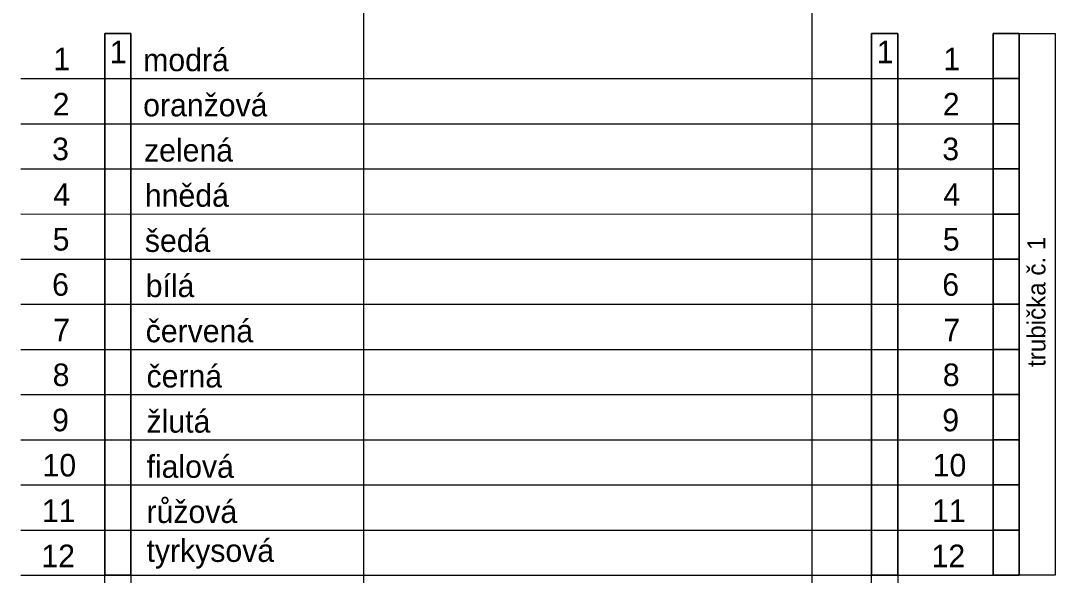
# Model space of a CAD drawing. Extents: x 1901 to 2519, y -3585 to -3154.
# Drawn here: x 2032.8 to 2113, y -3245.2 to -3202 of the extents above; entities that cross this region are included whole.
import ezdxf

# ---------------------------------------------------------------- set-up
doc = ezdxf.new("R2010")
doc.units = 0
doc.layers.add('rozvláknění', color=7, linetype='Continuous')

msp = doc.modelspace()

# ---------------------------------------------------------------- linework, layer by layer
at = {"layer": 'rozvláknění'}
for p, q in [((2032.823, -3206.524), (2108.565, -3206.527)), ((2032.823, -3210.043), (2108.565, -3210.045)), ((2032.823, -3213.561), (2108.565, -3213.563)), ((2032.823, -3217.079), (2108.565, -3217.081)), ((2032.823, -3220.597), (2108.565, -3220.599)), ((2032.823, -3224.115), (2108.565, -3224.117)), ((2032.823, -3227.634), (2108.565, -3227.636)), ((2032.823, -3231.152), (2108.565, -3231.154)), ((2032.823, -3234.67), (2108.565, -3234.672)), ((2032.823, -3238.188), (2108.565, -3238.19)), ((2032.823, -3241.706), (2108.565, -3241.708)), ((2032.823, -3245.225), (2108.565, -3245.227))]:
    msp.add_line(p, q, dxfattribs=at)
for points in [[(2014.869, -3178.545), (2059.522, -3178.544), (2059.522, -3570.656), (2014.869, -3570.656)], [(2094.462, -3178.545), (2128.46, -3178.544), (2128.46, -3571.465), (2094.462, -3571.465)], [(2041.391, -3287.481), (2039.35, -3287.481), (2039.35, -3203.008), (2041.391, -3203.008)], [(2041.391, -3245.227), (2039.35, -3245.227), (2039.35, -3203.008), (2041.391, -3203.008)], [(2101.143, -3287.481), (2099.102, -3287.481), (2099.102, -3203.008), (2101.143, -3203.008)], [(2101.143, -3245.227), (2099.102, -3245.227), (2099.102, -3203.008), (2101.143, -3203.008)], [(2108.565, -3203.008), (2110.606, -3203.008), (2110.606, -3206.527), (2108.565, -3206.527)], [(2108.565, -3203.008), (2110.606, -3203.008), (2110.606, -3206.527), (2108.565, -3206.527)], [(2110.606, -3203.008), (2113.393, -3203.008), (2113.393, -3245.223), (2110.606, -3245.223)], [(2108.565, -3206.527), (2110.606, -3206.527), (2110.606, -3210.045), (2108.565, -3210.045)], [(2108.565, -3206.527), (2110.606, -3206.527), (2110.606, -3210.045), (2108.565, -3210.045)], [(2108.565, -3210.045), (2110.606, -3210.045), (2110.606, -3213.563), (2108.565, -3213.563)], [(2108.565, -3210.045), (2110.606, -3210.045), (2110.606, -3213.563), (2108.565, -3213.563)], [(2108.565, -3213.563), (2110.606, -3213.563), (2110.606, -3217.081), (2108.565, -3217.081)], [(2108.565, -3213.563), (2110.606, -3213.563), (2110.606, -3217.081), (2108.565, -3217.081)], [(2108.565, -3217.081), (2110.606, -3217.081), (2110.606, -3220.599), (2108.565, -3220.599)], [(2108.565, -3217.081), (2110.606, -3217.081), (2110.606, -3220.599), (2108.565, -3220.599)], [(2108.565, -3220.599), (2110.606, -3220.599), (2110.606, -3224.117), (2108.565, -3224.117)], [(2108.565, -3220.599), (2110.606, -3220.599), (2110.606, -3224.117), (2108.565, -3224.117)], [(2108.565, -3224.117), (2110.606, -3224.117), (2110.606, -3227.636), (2108.565, -3227.636)], [(2108.565, -3224.117), (2110.606, -3224.117), (2110.606, -3227.636), (2108.565, -3227.636)], [(2108.565, -3227.636), (2110.606, -3227.636), (2110.606, -3231.154), (2108.565, -3231.154)], [(2108.565, -3227.636), (2110.606, -3227.636), (2110.606, -3231.154), (2108.565, -3231.154)], [(2108.565, -3231.154), (2110.606, -3231.154), (2110.606, -3234.672), (2108.565, -3234.672)], [(2108.565, -3231.154), (2110.606, -3231.154), (2110.606, -3234.672), (2108.565, -3234.672)], [(2108.565, -3234.672), (2110.606, -3234.672), (2110.606, -3238.19), (2108.565, -3238.19)], [(2108.565, -3234.672), (2110.606, -3234.672), (2110.606, -3238.19), (2108.565, -3238.19)], [(2108.565, -3238.19), (2110.606, -3238.19), (2110.606, -3241.708), (2108.565, -3241.708)], [(2108.565, -3238.19), (2110.606, -3238.19), (2110.606, -3241.708), (2108.565, -3241.708)], [(2108.565, -3241.708), (2110.606, -3241.708), (2110.606, -3245.227), (2108.565, -3245.227)], [(2108.565, -3241.708), (2110.606, -3241.708), (2110.606, -3245.227), (2108.565, -3245.227)]]:
    msp.add_lwpolyline(points, close=True, dxfattribs=at)
for points in [[(2041.391, -3203.008), (2039.35, -3203.008), (2039.35, -3245.227), (2041.391, -3245.227), (2041.391, -3203.008)], [(2041.391, -3203.008), (2039.35, -3203.008), (2039.35, -3245.227), (2041.391, -3245.227), (2041.391, -3203.008)], [(2041.391, -3203.008), (2039.35, -3203.008), (2039.35, -3245.227), (2041.391, -3245.227), (2041.391, -3203.008)], [(2041.391, -3203.008), (2039.35, -3203.008), (2039.35, -3245.227), (2041.391, -3245.227), (2041.391, -3203.008)], [(2041.391, -3203.008), (2039.35, -3203.008), (2039.35, -3245.227), (2041.391, -3245.227), (2041.391, -3203.008)], [(2041.391, -3203.008), (2039.35, -3203.008), (2039.35, -3245.227), (2041.391, -3245.227), (2041.391, -3203.008)], [(2101.143, -3203.008), (2099.102, -3203.008), (2099.102, -3245.227), (2101.143, -3245.227), (2101.143, -3203.008)], [(2101.143, -3203.008), (2099.102, -3203.008), (2099.102, -3245.227), (2101.143, -3245.227), (2101.143, -3203.008)], [(2101.143, -3203.008), (2099.102, -3203.008), (2099.102, -3245.227), (2101.143, -3245.227), (2101.143, -3203.008)], [(2101.143, -3203.008), (2099.102, -3203.008), (2099.102, -3245.227), (2101.143, -3245.227), (2101.143, -3203.008)], [(2101.143, -3203.008), (2099.102, -3203.008), (2099.102, -3245.227), (2101.143, -3245.227), (2101.143, -3203.008)], [(2101.143, -3203.008), (2099.102, -3203.008), (2099.102, -3245.227), (2101.143, -3245.227), (2101.143, -3203.008)], [(2108.565, -3206.527), (2110.606, -3206.527), (2110.606, -3203.008), (2108.565, -3203.008), (2108.565, -3206.527)], [(2108.565, -3206.527), (2110.606, -3206.527), (2110.606, -3203.008), (2108.565, -3203.008), (2108.565, -3206.527)], [(2108.565, -3206.527), (2110.606, -3206.527), (2110.606, -3203.008), (2108.565, -3203.008), (2108.565, -3206.527)], [(2108.565, -3206.527), (2110.606, -3206.527), (2110.606, -3203.008), (2108.565, -3203.008), (2108.565, -3206.527)], [(2108.565, -3206.527), (2110.606, -3206.527), (2110.606, -3203.008), (2108.565, -3203.008), (2108.565, -3206.527)], [(2108.565, -3206.527), (2110.606, -3206.527), (2110.606, -3203.008), (2108.565, -3203.008), (2108.565, -3206.527)], [(2108.565, -3206.527), (2110.606, -3206.527), (2110.606, -3203.008), (2108.565, -3203.008), (2108.565, -3206.527)], [(2108.565, -3206.527), (2110.606, -3206.527), (2110.606, -3203.008), (2108.565, -3203.008), (2108.565, -3206.527)], [(2108.565, -3206.527), (2110.606, -3206.527), (2110.606, -3203.008), (2108.565, -3203.008), (2108.565, -3206.527)], [(2108.565, -3206.527), (2110.606, -3206.527), (2110.606, -3203.008), (2108.565, -3203.008), (2108.565, -3206.527)], [(2108.565, -3210.045), (2110.606, -3210.045), (2110.606, -3206.527), (2108.565, -3206.527), (2108.565, -3210.045)], [(2108.565, -3210.045), (2110.606, -3210.045), (2110.606, -3206.527), (2108.565, -3206.527), (2108.565, -3210.045)], [(2108.565, -3210.045), (2110.606, -3210.045), (2110.606, -3206.527), (2108.565, -3206.527), (2108.565, -3210.045)], [(2108.565, -3210.045), (2110.606, -3210.045), (2110.606, -3206.527), (2108.565, -3206.527), (2108.565, -3210.045)], [(2108.565, -3210.045), (2110.606, -3210.045), (2110.606, -3206.527), (2108.565, -3206.527), (2108.565, -3210.045)], [(2108.565, -3210.045), (2110.606, -3210.045), (2110.606, -3206.527), (2108.565, -3206.527), (2108.565, -3210.045)], [(2108.565, -3210.045), (2110.606, -3210.045), (2110.606, -3206.527), (2108.565, -3206.527), (2108.565, -3210.045)], [(2108.565, -3210.045), (2110.606, -3210.045), (2110.606, -3206.527), (2108.565, -3206.527), (2108.565, -3210.045)], [(2108.565, -3210.045), (2110.606, -3210.045), (2110.606, -3206.527), (2108.565, -3206.527), (2108.565, -3210.045)], [(2108.565, -3210.045), (2110.606, -3210.045), (2110.606, -3206.527), (2108.565, -3206.527), (2108.565, -3210.045)], [(2108.565, -3213.563), (2110.606, -3213.563), (2110.606, -3210.045), (2108.565, -3210.045), (2108.565, -3213.563)], [(2108.565, -3213.563), (2110.606, -3213.563), (2110.606, -3210.045), (2108.565, -3210.045), (2108.565, -3213.563)], [(2108.565, -3213.563), (2110.606, -3213.563), (2110.606, -3210.045), (2108.565, -3210.045), (2108.565, -3213.563)], [(2108.565, -3213.563), (2110.606, -3213.563), (2110.606, -3210.045), (2108.565, -3210.045), (2108.565, -3213.563)], [(2108.565, -3213.563), (2110.606, -3213.563), (2110.606, -3210.045), (2108.565, -3210.045), (2108.565, -3213.563)], [(2108.565, -3213.563), (2110.606, -3213.563), (2110.606, -3210.045), (2108.565, -3210.045), (2108.565, -3213.563)], [(2108.565, -3213.563), (2110.606, -3213.563), (2110.606, -3210.045), (2108.565, -3210.045), (2108.565, -3213.563)], [(2108.565, -3213.563), (2110.606, -3213.563), (2110.606, -3210.045), (2108.565, -3210.045), (2108.565, -3213.563)], [(2108.565, -3213.563), (2110.606, -3213.563), (2110.606, -3210.045), (2108.565, -3210.045), (2108.565, -3213.563)], [(2108.565, -3213.563), (2110.606, -3213.563), (2110.606, -3210.045), (2108.565, -3210.045), (2108.565, -3213.563)], [(2108.565, -3217.081), (2110.606, -3217.081), (2110.606, -3213.563), (2108.565, -3213.563), (2108.565, -3217.081)], [(2108.565, -3217.081), (2110.606, -3217.081), (2110.606, -3213.563), (2108.565, -3213.563), (2108.565, -3217.081)], [(2108.565, -3217.081), (2110.606, -3217.081), (2110.606, -3213.563), (2108.565, -3213.563), (2108.565, -3217.081)], [(2108.565, -3217.081), (2110.606, -3217.081), (2110.606, -3213.563), (2108.565, -3213.563), (2108.565, -3217.081)], [(2108.565, -3217.081), (2110.606, -3217.081), (2110.606, -3213.563), (2108.565, -3213.563), (2108.565, -3217.081)], [(2108.565, -3217.081), (2110.606, -3217.081), (2110.606, -3213.563), (2108.565, -3213.563), (2108.565, -3217.081)], [(2108.565, -3217.081), (2110.606, -3217.081), (2110.606, -3213.563), (2108.565, -3213.563), (2108.565, -3217.081)], [(2108.565, -3217.081), (2110.606, -3217.081), (2110.606, -3213.563), (2108.565, -3213.563), (2108.565, -3217.081)], [(2108.565, -3217.081), (2110.606, -3217.081), (2110.606, -3213.563), (2108.565, -3213.563), (2108.565, -3217.081)], [(2108.565, -3217.081), (2110.606, -3217.081), (2110.606, -3213.563), (2108.565, -3213.563), (2108.565, -3217.081)], [(2108.565, -3220.599), (2110.606, -3220.599), (2110.606, -3217.081), (2108.565, -3217.081), (2108.565, -3220.599)], [(2108.565, -3220.599), (2110.606, -3220.599), (2110.606, -3217.081), (2108.565, -3217.081), (2108.565, -3220.599)], [(2108.565, -3220.599), (2110.606, -3220.599), (2110.606, -3217.081), (2108.565, -3217.081), (2108.565, -3220.599)], [(2108.565, -3220.599), (2110.606, -3220.599), (2110.606, -3217.081), (2108.565, -3217.081), (2108.565, -3220.599)], [(2108.565, -3220.599), (2110.606, -3220.599), (2110.606, -3217.081), (2108.565, -3217.081), (2108.565, -3220.599)], [(2108.565, -3220.599), (2110.606, -3220.599), (2110.606, -3217.081), (2108.565, -3217.081), (2108.565, -3220.599)], [(2108.565, -3220.599), (2110.606, -3220.599), (2110.606, -3217.081), (2108.565, -3217.081), (2108.565, -3220.599)], [(2108.565, -3220.599), (2110.606, -3220.599), (2110.606, -3217.081), (2108.565, -3217.081), (2108.565, -3220.599)], [(2108.565, -3220.599), (2110.606, -3220.599), (2110.606, -3217.081), (2108.565, -3217.081), (2108.565, -3220.599)], [(2108.565, -3220.599), (2110.606, -3220.599), (2110.606, -3217.081), (2108.565, -3217.081), (2108.565, -3220.599)], [(2108.565, -3224.117), (2110.606, -3224.117), (2110.606, -3220.599), (2108.565, -3220.599), (2108.565, -3224.117)], [(2108.565, -3224.117), (2110.606, -3224.117), (2110.606, -3220.599), (2108.565, -3220.599), (2108.565, -3224.117)], [(2108.565, -3224.117), (2110.606, -3224.117), (2110.606, -3220.599), (2108.565, -3220.599), (2108.565, -3224.117)], [(2108.565, -3224.117), (2110.606, -3224.117), (2110.606, -3220.599), (2108.565, -3220.599), (2108.565, -3224.117)], [(2108.565, -3224.117), (2110.606, -3224.117), (2110.606, -3220.599), (2108.565, -3220.599), (2108.565, -3224.117)], [(2108.565, -3224.117), (2110.606, -3224.117), (2110.606, -3220.599), (2108.565, -3220.599), (2108.565, -3224.117)], [(2108.565, -3224.117), (2110.606, -3224.117), (2110.606, -3220.599), (2108.565, -3220.599), (2108.565, -3224.117)], [(2108.565, -3224.117), (2110.606, -3224.117), (2110.606, -3220.599), (2108.565, -3220.599), (2108.565, -3224.117)], [(2108.565, -3224.117), (2110.606, -3224.117), (2110.606, -3220.599), (2108.565, -3220.599), (2108.565, -3224.117)], [(2108.565, -3224.117), (2110.606, -3224.117), (2110.606, -3220.599), (2108.565, -3220.599), (2108.565, -3224.117)], [(2108.565, -3227.636), (2110.606, -3227.636), (2110.606, -3224.117), (2108.565, -3224.117), (2108.565, -3227.636)], [(2108.565, -3227.636), (2110.606, -3227.636), (2110.606, -3224.117), (2108.565, -3224.117), (2108.565, -3227.636)], [(2108.565, -3227.636), (2110.606, -3227.636), (2110.606, -3224.117), (2108.565, -3224.117), (2108.565, -3227.636)], [(2108.565, -3227.636), (2110.606, -3227.636), (2110.606, -3224.117), (2108.565, -3224.117), (2108.565, -3227.636)], [(2108.565, -3227.636), (2110.606, -3227.636), (2110.606, -3224.117), (2108.565, -3224.117), (2108.565, -3227.636)], [(2108.565, -3227.636), (2110.606, -3227.636), (2110.606, -3224.117), (2108.565, -3224.117), (2108.565, -3227.636)], [(2108.565, -3227.636), (2110.606, -3227.636), (2110.606, -3224.117), (2108.565, -3224.117), (2108.565, -3227.636)], [(2108.565, -3227.636), (2110.606, -3227.636), (2110.606, -3224.117), (2108.565, -3224.117), (2108.565, -3227.636)], [(2108.565, -3227.636), (2110.606, -3227.636), (2110.606, -3224.117), (2108.565, -3224.117), (2108.565, -3227.636)], [(2108.565, -3227.636), (2110.606, -3227.636), (2110.606, -3224.117), (2108.565, -3224.117), (2108.565, -3227.636)], [(2108.565, -3231.154), (2110.606, -3231.154), (2110.606, -3227.636), (2108.565, -3227.636), (2108.565, -3231.154)], [(2108.565, -3231.154), (2110.606, -3231.154), (2110.606, -3227.636), (2108.565, -3227.636), (2108.565, -3231.154)], [(2108.565, -3231.154), (2110.606, -3231.154), (2110.606, -3227.636), (2108.565, -3227.636), (2108.565, -3231.154)], [(2108.565, -3231.154), (2110.606, -3231.154), (2110.606, -3227.636), (2108.565, -3227.636), (2108.565, -3231.154)], [(2108.565, -3231.154), (2110.606, -3231.154), (2110.606, -3227.636), (2108.565, -3227.636), (2108.565, -3231.154)], [(2108.565, -3231.154), (2110.606, -3231.154), (2110.606, -3227.636), (2108.565, -3227.636), (2108.565, -3231.154)], [(2108.565, -3231.154), (2110.606, -3231.154), (2110.606, -3227.636), (2108.565, -3227.636), (2108.565, -3231.154)], [(2108.565, -3231.154), (2110.606, -3231.154), (2110.606, -3227.636), (2108.565, -3227.636), (2108.565, -3231.154)], [(2108.565, -3231.154), (2110.606, -3231.154), (2110.606, -3227.636), (2108.565, -3227.636), (2108.565, -3231.154)], [(2108.565, -3231.154), (2110.606, -3231.154), (2110.606, -3227.636), (2108.565, -3227.636), (2108.565, -3231.154)], [(2108.565, -3234.672), (2110.606, -3234.672), (2110.606, -3231.154), (2108.565, -3231.154), (2108.565, -3234.672)], [(2108.565, -3234.672), (2110.606, -3234.672), (2110.606, -3231.154), (2108.565, -3231.154), (2108.565, -3234.672)], [(2108.565, -3234.672), (2110.606, -3234.672), (2110.606, -3231.154), (2108.565, -3231.154), (2108.565, -3234.672)], [(2108.565, -3234.672), (2110.606, -3234.672), (2110.606, -3231.154), (2108.565, -3231.154), (2108.565, -3234.672)], [(2108.565, -3234.672), (2110.606, -3234.672), (2110.606, -3231.154), (2108.565, -3231.154), (2108.565, -3234.672)], [(2108.565, -3234.672), (2110.606, -3234.672), (2110.606, -3231.154), (2108.565, -3231.154), (2108.565, -3234.672)], [(2108.565, -3234.672), (2110.606, -3234.672), (2110.606, -3231.154), (2108.565, -3231.154), (2108.565, -3234.672)], [(2108.565, -3234.672), (2110.606, -3234.672), (2110.606, -3231.154), (2108.565, -3231.154), (2108.565, -3234.672)], [(2108.565, -3234.672), (2110.606, -3234.672), (2110.606, -3231.154), (2108.565, -3231.154), (2108.565, -3234.672)], [(2108.565, -3234.672), (2110.606, -3234.672), (2110.606, -3231.154), (2108.565, -3231.154), (2108.565, -3234.672)], [(2108.565, -3238.19), (2110.606, -3238.19), (2110.606, -3234.672), (2108.565, -3234.672), (2108.565, -3238.19)], [(2108.565, -3238.19), (2110.606, -3238.19), (2110.606, -3234.672), (2108.565, -3234.672), (2108.565, -3238.19)], [(2108.565, -3238.19), (2110.606, -3238.19), (2110.606, -3234.672), (2108.565, -3234.672), (2108.565, -3238.19)], [(2108.565, -3238.19), (2110.606, -3238.19), (2110.606, -3234.672), (2108.565, -3234.672), (2108.565, -3238.19)], [(2108.565, -3238.19), (2110.606, -3238.19), (2110.606, -3234.672), (2108.565, -3234.672), (2108.565, -3238.19)], [(2108.565, -3238.19), (2110.606, -3238.19), (2110.606, -3234.672), (2108.565, -3234.672), (2108.565, -3238.19)], [(2108.565, -3238.19), (2110.606, -3238.19), (2110.606, -3234.672), (2108.565, -3234.672), (2108.565, -3238.19)], [(2108.565, -3238.19), (2110.606, -3238.19), (2110.606, -3234.672), (2108.565, -3234.672), (2108.565, -3238.19)], [(2108.565, -3238.19), (2110.606, -3238.19), (2110.606, -3234.672), (2108.565, -3234.672), (2108.565, -3238.19)], [(2108.565, -3238.19), (2110.606, -3238.19), (2110.606, -3234.672), (2108.565, -3234.672), (2108.565, -3238.19)], [(2108.565, -3241.708), (2110.606, -3241.708), (2110.606, -3238.19), (2108.565, -3238.19), (2108.565, -3241.708)], [(2108.565, -3241.708), (2110.606, -3241.708), (2110.606, -3238.19), (2108.565, -3238.19), (2108.565, -3241.708)], [(2108.565, -3241.708), (2110.606, -3241.708), (2110.606, -3238.19), (2108.565, -3238.19), (2108.565, -3241.708)], [(2108.565, -3241.708), (2110.606, -3241.708), (2110.606, -3238.19), (2108.565, -3238.19), (2108.565, -3241.708)], [(2108.565, -3241.708), (2110.606, -3241.708), (2110.606, -3238.19), (2108.565, -3238.19), (2108.565, -3241.708)], [(2108.565, -3241.708), (2110.606, -3241.708), (2110.606, -3238.19), (2108.565, -3238.19), (2108.565, -3241.708)], [(2108.565, -3241.708), (2110.606, -3241.708), (2110.606, -3238.19), (2108.565, -3238.19), (2108.565, -3241.708)], [(2108.565, -3241.708), (2110.606, -3241.708), (2110.606, -3238.19), (2108.565, -3238.19), (2108.565, -3241.708)], [(2108.565, -3241.708), (2110.606, -3241.708), (2110.606, -3238.19), (2108.565, -3238.19), (2108.565, -3241.708)], [(2108.565, -3241.708), (2110.606, -3241.708), (2110.606, -3238.19), (2108.565, -3238.19), (2108.565, -3241.708)], [(2108.565, -3245.227), (2110.606, -3245.227), (2110.606, -3241.708), (2108.565, -3241.708), (2108.565, -3245.227)], [(2108.565, -3245.227), (2110.606, -3245.227), (2110.606, -3241.708), (2108.565, -3241.708), (2108.565, -3245.227)], [(2108.565, -3245.227), (2110.606, -3245.227), (2110.606, -3241.708), (2108.565, -3241.708), (2108.565, -3245.227)], [(2108.565, -3245.227), (2110.606, -3245.227), (2110.606, -3241.708), (2108.565, -3241.708), (2108.565, -3245.227)], [(2108.565, -3245.227), (2110.606, -3245.227), (2110.606, -3241.708), (2108.565, -3241.708), (2108.565, -3245.227)], [(2108.565, -3245.227), (2110.606, -3245.227), (2110.606, -3241.708), (2108.565, -3241.708), (2108.565, -3245.227)], [(2108.565, -3245.227), (2110.606, -3245.227), (2110.606, -3241.708), (2108.565, -3241.708), (2108.565, -3245.227)], [(2108.565, -3245.227), (2110.606, -3245.227), (2110.606, -3241.708), (2108.565, -3241.708), (2108.565, -3245.227)], [(2108.565, -3245.227), (2110.606, -3245.227), (2110.606, -3241.708), (2108.565, -3241.708), (2108.565, -3245.227)], [(2108.565, -3245.227), (2110.606, -3245.227), (2110.606, -3241.708), (2108.565, -3241.708), (2108.565, -3245.227)]]:
    msp.add_lwpolyline(points, dxfattribs=at)

# ---------------------------------------------------------------- texts
for s, p in [('1', (2039.749, -3205.334)), ('1', (2039.749, -3205.334)), ('1', (2099.501, -3205.334)), ('1', (2099.501, -3205.334)), ('1', (2035.34, -3205.88)), ('modrá', (2042.346, -3205.953)), ('1', (2104.694, -3205.88)), ('2', (2035.294, -3209.4)), ('oranžová', (2042.346, -3209.473)), ('2', (2104.647, -3209.4)), ('3', (2035.251, -3212.89)), ('zelená', (2042.411, -3212.993)), ('3', (2104.605, -3212.89)), ('4', (2035.34, -3216.44)), ('hnědá', (2042.477, -3216.513)), ('4', (2104.694, -3216.44)), ('5', (2035.294, -3219.93)), ('šedá', (2042.477, -3220.033)), ('5', (2104.647, -3219.93)), ('6', (2035.251, -3223.45)), ('bílá', (2042.542, -3223.553)), ('6', (2104.605, -3223.45)), ('7', (2035.34, -3227)), ('červená', (2042.542, -3227.073)), ('7', (2104.694, -3227)), ('8', (2035.294, -3230.49)), ('černá', (2042.608, -3230.593)), ('8', (2104.647, -3230.49)), ('9', (2035.251, -3234.01)), ('žlutá', (2042.608, -3234.113)), ('9', (2104.605, -3234.01)), ('10', (2034.503, -3237.53)), ('fialová', (2042.608, -3237.633)), ('10', (2103.857, -3237.53)), ('11', (2034.456, -3241.08)), ('růžová', (2042.608, -3241.153)), ('11', (2103.81, -3241.08)), ('12', (2034.414, -3244.6)), ('tyrkysová', (2042.608, -3244.185)), ('12', (2103.768, -3244.6))]:
    msp.add_text(s, height=1.76, dxfattribs=at).set_placement(p)
msp.add_text('trubička č. 1', height=1.408, rotation=90, dxfattribs=at).set_placement((2112.642, -3228.997))

doc.saveas('drawing.dxf')
